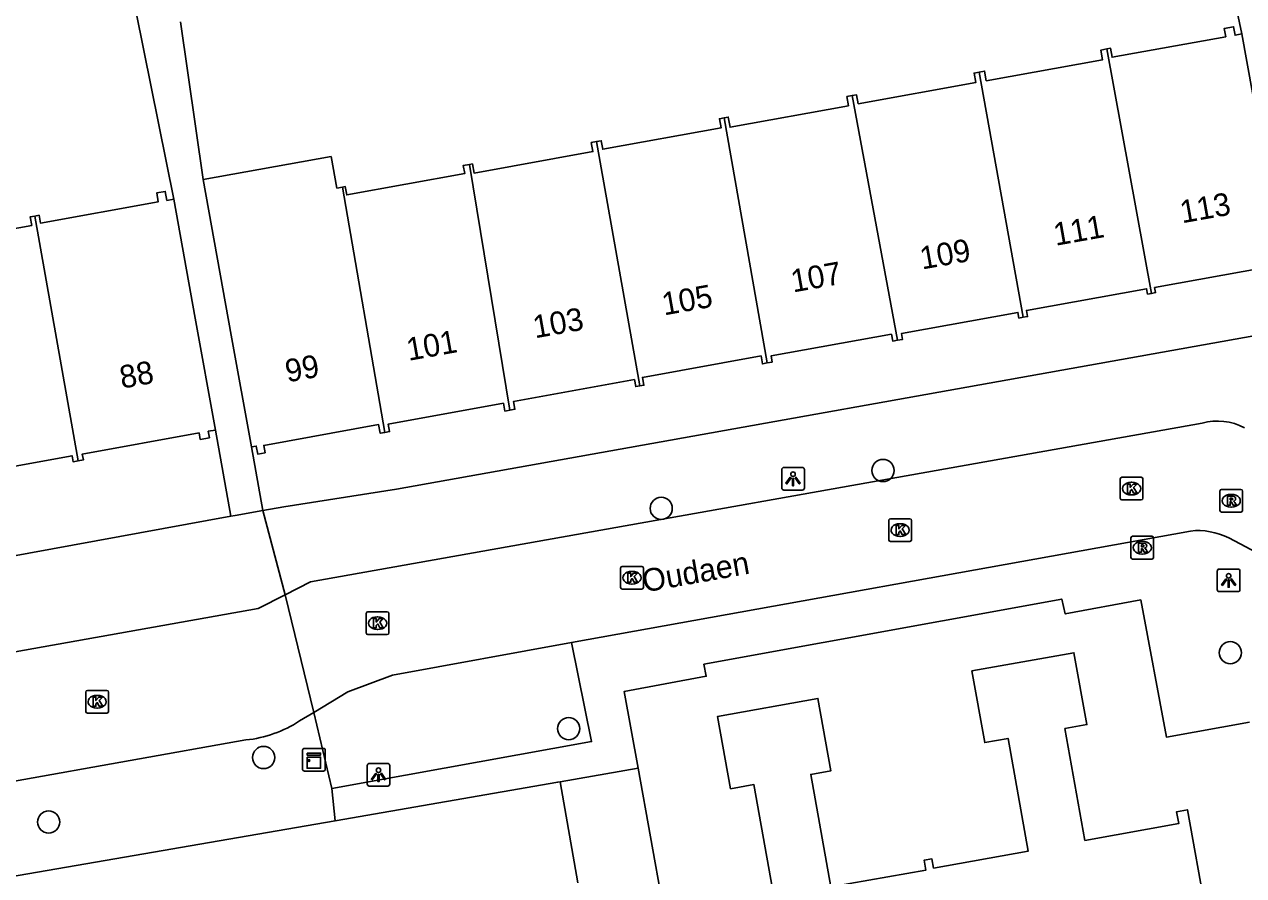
# Model space of a CAD drawing. Extents: x 157793 to 159380, y 380882 to 382313.
# Drawn here: x 158378.2 to 158431.9, y 381426.5 to 381464 of the extents above; entities that cross this region are included whole.
import ezdxf

# ---------------------------------------------------------------- set-up
doc = ezdxf.new("R2010")
doc.units = 0
for name, color, linetype in [('IMGEO_Boom', 7, 'Continuous'), ('IMGEO_Kast', 7, 'Continuous'), ('IMGEO_Kolk', 7, 'Continuous'), ('IMGEO_Lichtpunt', 7, 'Continuous'), ('IMGEO_Openbare_ruimte_label', 7, 'Continuous'), ('IMGEO_Pand', 7, 'Continuous'), ('IMGEO_Pand_nummerreeks', 7, 'Continuous'), ('IMGEO_Rijbaan_lokaal_open', 7, 'Continuous'), ('IMGEO_Rioolput', 7, 'Continuous'), ('IMGEO_Voetpad_open', 7, 'Continuous')]:
    doc.layers.add(name, color=color, linetype=linetype)

msp = doc.modelspace()

# ---------------------------------------------------------------- linework, layer by layer
at = {"layer": 'IMGEO_Boom'}
for centre in [(158416.009, 381444.352), (158406.245, 381442.684), (158431.298, 381436.33), (158402.174, 381432.988), (158388.741, 381431.716), (158379.274, 381428.878)]:
    msp.add_circle(centre, 0.489, dxfattribs=at)
at = {"layer": 'IMGEO_Kast'}
for p, q in [((158390.455, 381431.196), (158390.455, 381432.037)), ((158390.455, 381432.037), (158390.455, 381431.196)), ((158390.53, 381432.121), (158391.371, 381432.121)), ((158391.371, 381432.121), (158390.53, 381432.121)), ((158391.455, 381432.046), (158391.455, 381431.205)), ((158391.455, 381431.205), (158391.455, 381432.046)), ((158391.38, 381431.121), (158390.539, 381431.121)), ((158390.539, 381431.121), (158391.38, 381431.121))]:
    msp.add_line(p, q, dxfattribs=at)
for points in [[(158390.65, 381431.911), (158391.25, 381431.911), (158391.25, 381431.826), (158390.65, 381431.826), (158390.65, 381431.911)], [(158390.65, 381431.736), (158391.25, 381431.736), (158391.25, 381431.247), (158390.65, 381431.247), (158390.65, 381431.736)]]:
    msp.add_lwpolyline(points, dxfattribs=at)
msp.add_circle((158390.734, 381431.585), 0.0377, dxfattribs=at)
for centre, start, end in [((158390.533, 381432.043), 92.4484, 184.2845), ((158390.533, 381432.043), 92.4484, 184.2845), ((158391.377, 381432.043), 2.4484, 94.2845), ((158391.377, 381432.043), 2.4484, 94.2845), ((158390.533, 381431.199), 182.4484, 274.2845), ((158390.533, 381431.199), 182.4484, 274.2845), ((158391.377, 381431.199), 272.4484, 4.2845), ((158391.377, 381431.199), 272.4484, 4.2845)]:
    msp.add_arc(centre, 0.0779, start, end, dxfattribs=at)
at = {"layer": 'IMGEO_Kolk'}
for p, q in [((158426.452, 381443.131), (158426.452, 381443.983)), ((158426.527, 381444.057), (158427.379, 381444.057)), ((158426.94, 381443.837), (158426.965, 381443.837)), ((158427.453, 381443.983), (158427.453, 381443.131)), ((158426.963, 381443.277), (158426.938, 381443.277)), ((158427.379, 381443.057), (158426.527, 381443.057)), ((158416.263, 381441.304), (158416.263, 381442.156)), ((158416.338, 381442.23), (158417.19, 381442.23)), ((158416.751, 381442.01), (158416.776, 381442.01)), ((158417.264, 381442.156), (158417.264, 381441.304)), ((158416.774, 381441.45), (158416.749, 381441.45)), ((158417.19, 381441.23), (158416.338, 381441.23)), ((158404.457, 381439.206), (158404.457, 381440.058)), ((158404.532, 381440.132), (158405.384, 381440.132)), ((158404.945, 381439.912), (158404.97, 381439.912)), ((158405.458, 381440.058), (158405.458, 381439.206)), ((158404.968, 381439.352), (158404.943, 381439.352)), ((158405.384, 381439.132), (158404.532, 381439.132)), ((158393.257, 381437.205), (158393.257, 381438.057)), ((158393.332, 381438.131), (158394.184, 381438.131)), ((158393.745, 381437.911), (158393.77, 381437.911)), ((158394.258, 381438.057), (158394.258, 381437.205)), ((158393.768, 381437.351), (158393.743, 381437.351)), ((158394.184, 381437.131), (158393.332, 381437.131)), ((158380.909, 381433.748), (158380.909, 381434.6)), ((158380.984, 381434.674), (158381.836, 381434.674)), ((158381.91, 381434.6), (158381.91, 381433.748)), ((158381.397, 381434.454), (158381.422, 381434.454)), ((158381.836, 381433.674), (158380.984, 381433.674)), ((158381.42, 381433.894), (158381.395, 381433.894))]:
    msp.add_line(p, q, dxfattribs=at)
for points in [[(158426.452, 381443.131), (158426.452, 381443.983)], [(158426.527, 381444.057), (158427.379, 381444.057)], [(158426.773, 381443.757), (158426.896, 381443.757), (158426.896, 381443.606), (158427.026, 381443.757), (158427.19, 381443.757), (158427.044, 381443.606), (158427.197, 381443.357), (158427.045, 381443.357), (158426.96, 381443.521), (158426.896, 381443.454), (158426.896, 381443.357), (158426.773, 381443.357), (158426.773, 381443.757)], [(158427.453, 381443.983), (158427.453, 381443.131)], [(158427.379, 381443.057), (158426.527, 381443.057)], [(158416.263, 381441.304), (158416.263, 381442.156)], [(158416.338, 381442.23), (158417.19, 381442.23)], [(158417.264, 381442.156), (158417.264, 381441.304)], [(158416.584, 381441.93), (158416.707, 381441.93), (158416.707, 381441.779), (158416.837, 381441.93), (158417.001, 381441.93), (158416.855, 381441.779), (158417.008, 381441.53), (158416.856, 381441.53), (158416.771, 381441.694), (158416.707, 381441.627), (158416.707, 381441.53), (158416.584, 381441.53), (158416.584, 381441.93)], [(158417.19, 381441.23), (158416.338, 381441.23)], [(158404.457, 381439.206), (158404.457, 381440.058)], [(158404.532, 381440.132), (158405.384, 381440.132)], [(158405.458, 381440.058), (158405.458, 381439.206)], [(158404.778, 381439.832), (158404.901, 381439.832), (158404.901, 381439.681), (158405.031, 381439.832), (158405.195, 381439.832), (158405.049, 381439.681), (158405.202, 381439.432), (158405.05, 381439.432), (158404.965, 381439.596), (158404.901, 381439.529), (158404.901, 381439.432), (158404.778, 381439.432), (158404.778, 381439.832)], [(158405.384, 381439.132), (158404.532, 381439.132)], [(158393.257, 381437.205), (158393.257, 381438.057)], [(158393.332, 381438.131), (158394.184, 381438.131)], [(158393.578, 381437.831), (158393.701, 381437.831), (158393.701, 381437.68), (158393.831, 381437.831), (158393.995, 381437.831), (158393.849, 381437.68), (158394.002, 381437.431), (158393.85, 381437.431), (158393.765, 381437.595), (158393.701, 381437.528), (158393.701, 381437.431), (158393.578, 381437.431), (158393.578, 381437.831)], [(158394.258, 381438.057), (158394.258, 381437.205)], [(158394.184, 381437.131), (158393.332, 381437.131)], [(158380.909, 381433.748), (158380.909, 381434.6)], [(158380.984, 381434.674), (158381.836, 381434.674)], [(158381.91, 381434.6), (158381.91, 381433.748)], [(158381.23, 381434.374), (158381.353, 381434.374), (158381.353, 381434.223), (158381.483, 381434.374), (158381.647, 381434.374), (158381.501, 381434.223), (158381.654, 381433.974), (158381.502, 381433.974), (158381.417, 381434.138), (158381.353, 381434.071), (158381.353, 381433.974), (158381.23, 381433.974), (158381.23, 381434.374)], [(158381.836, 381433.674), (158380.984, 381433.674)]]:
    msp.add_lwpolyline(points, dxfattribs=at)
for centre, start, end in [((158426.529, 381443.981), 91.552, 178.448), ((158426.529, 381443.981), 91.552, 178.448), ((158427.377, 381443.981), 1.552, 88.448), ((158427.377, 381443.981), 1.552, 88.448), ((158426.529, 381443.133), 181.552, 268.448), ((158426.529, 381443.133), 181.552, 268.448), ((158427.377, 381443.133), 271.552, 358.448), ((158427.377, 381443.133), 271.552, 358.448), ((158416.34, 381442.154), 91.552, 178.448), ((158416.34, 381442.154), 91.552, 178.448), ((158417.188, 381442.154), 1.552, 88.448), ((158417.188, 381442.154), 1.552, 88.448), ((158416.34, 381441.306), 181.552, 268.448), ((158416.34, 381441.306), 181.552, 268.448), ((158417.188, 381441.306), 271.552, 358.448), ((158417.188, 381441.306), 271.552, 358.448), ((158404.534, 381440.056), 91.552, 178.448), ((158404.534, 381440.056), 91.552, 178.448), ((158405.382, 381440.056), 1.552, 88.448), ((158405.382, 381440.056), 1.552, 88.448), ((158404.534, 381439.208), 181.552, 268.448), ((158404.534, 381439.208), 181.552, 268.448), ((158405.382, 381439.208), 271.552, 358.448), ((158405.382, 381439.208), 271.552, 358.448), ((158393.334, 381438.055), 91.552, 178.448), ((158393.334, 381438.055), 91.552, 178.448), ((158394.182, 381438.055), 1.552, 88.448), ((158394.182, 381438.055), 1.552, 88.448), ((158393.334, 381437.207), 181.552, 268.448), ((158393.334, 381437.207), 181.552, 268.448), ((158394.182, 381437.207), 271.552, 358.448), ((158394.182, 381437.207), 271.552, 358.448), ((158380.986, 381434.598), 91.552, 178.448), ((158380.986, 381434.598), 91.552, 178.448), ((158381.834, 381434.598), 1.552, 88.448), ((158381.834, 381434.598), 1.552, 88.448), ((158380.986, 381433.75), 181.552, 268.448), ((158380.986, 381433.75), 181.552, 268.448), ((158381.834, 381433.75), 271.552, 358.448), ((158381.834, 381433.75), 271.552, 358.448)]:
    msp.add_arc(centre, 0.0765, start, end, dxfattribs=at)
for centre, major_axis, ratio, start_param, end_param in [((158426.939, 381443.557), (-0.387, 0.002), 0.722429, 4.712389, 7.853982), ((158426.964, 381443.557), (-0.39, 0.002), 0.717154, 1.570796, 4.712389), ((158416.75, 381441.73), (-0.387, 0.002), 0.722429, 4.712389, 7.853982), ((158416.775, 381441.73), (-0.39, 0.002), 0.717154, 1.570796, 4.712389), ((158404.944, 381439.632), (-0.387, 0.002), 0.722429, 4.712389, 7.853982), ((158404.969, 381439.632), (-0.39, 0.002), 0.717154, 1.570796, 4.712389), ((158393.744, 381437.631), (-0.387, 0.002), 0.722429, 4.712389, 7.853982), ((158393.769, 381437.631), (-0.39, 0.002), 0.717154, 1.570796, 4.712389), ((158381.396, 381434.174), (-0.387, 0.002), 0.722429, 4.712389, 7.853982), ((158381.421, 381434.174), (-0.39, 0.002), 0.717154, 1.570796, 4.712389)]:
    msp.add_ellipse(centre, major_axis=major_axis, ratio=ratio, start_param=start_param, end_param=end_param, dxfattribs=at)
at = {"layer": 'IMGEO_Lichtpunt'}
for p, q in [((158411.551, 381444.39), (158411.551, 381443.583)), ((158411.551, 381444.39), (158411.551, 381443.583)), ((158412.453, 381444.485), (158411.645, 381444.485)), ((158412.453, 381444.485), (158411.645, 381444.485)), ((158412.547, 381443.583), (158412.547, 381444.39)), ((158412.547, 381443.583), (158412.547, 381444.39)), ((158411.645, 381443.489), (158412.453, 381443.489)), ((158411.645, 381443.489), (158412.453, 381443.489)), ((158430.729, 381439.92), (158430.729, 381439.113)), ((158430.729, 381439.92), (158430.729, 381439.113)), ((158431.631, 381440.015), (158430.823, 381440.015)), ((158431.631, 381440.015), (158430.823, 381440.015)), ((158431.725, 381439.113), (158431.725, 381439.92)), ((158431.725, 381439.113), (158431.725, 381439.92)), ((158430.823, 381439.019), (158431.631, 381439.019)), ((158430.823, 381439.019), (158431.631, 381439.019)), ((158393.299, 381431.36), (158393.299, 381430.553)), ((158393.299, 381431.36), (158393.299, 381430.553)), ((158394.201, 381431.455), (158393.393, 381431.455)), ((158394.201, 381431.455), (158393.393, 381431.455)), ((158394.295, 381430.553), (158394.295, 381431.36)), ((158394.295, 381430.553), (158394.295, 381431.36)), ((158393.393, 381430.459), (158394.201, 381430.459)), ((158393.393, 381430.459), (158394.201, 381430.459))]:
    msp.add_line(p, q, dxfattribs=at)
for points in [[(158411.925, 381444.054), (158411.964, 381444.026), (158411.776, 381443.764), (158411.738, 381443.791), (158411.925, 381444.054)], [(158412.027, 381444.006), (158412.074, 381444.006), (158412.074, 381443.684), (158412.027, 381443.684), (158412.027, 381444.006)], [(158412.137, 381444.026), (158412.175, 381444.053), (158412.362, 381443.791), (158412.323, 381443.763), (158412.137, 381444.026)], [(158431.103, 381439.584), (158431.142, 381439.556), (158430.954, 381439.294), (158430.916, 381439.321), (158431.103, 381439.584)], [(158431.205, 381439.536), (158431.252, 381439.536), (158431.252, 381439.214), (158431.205, 381439.214), (158431.205, 381439.536)], [(158431.315, 381439.556), (158431.353, 381439.583), (158431.54, 381439.321), (158431.501, 381439.293), (158431.315, 381439.556)], [(158393.673, 381431.024), (158393.712, 381430.996), (158393.524, 381430.734), (158393.486, 381430.761), (158393.673, 381431.024)], [(158393.775, 381430.976), (158393.822, 381430.976), (158393.822, 381430.654), (158393.775, 381430.654), (158393.775, 381430.976)], [(158393.885, 381430.996), (158393.923, 381431.023), (158394.11, 381430.761), (158394.071, 381430.733), (158393.885, 381430.996)]]:
    msp.add_lwpolyline(points, dxfattribs=at)
for centre in [(158412.05, 381444.188), (158431.228, 381439.718), (158393.798, 381431.158)]:
    msp.add_circle(centre, 0.0994, dxfattribs=at)
for centre, start, end in [((158411.645, 381444.39), 90, 180), ((158411.645, 381444.39), 90, 180), ((158412.453, 381444.39), 0, 90), ((158412.453, 381444.39), 0, 90), ((158411.645, 381443.583), 180, 270), ((158411.645, 381443.583), 180, 270), ((158412.453, 381443.583), 270, 0), ((158412.453, 381443.583), 270, 360), ((158430.823, 381439.92), 90, 180), ((158430.823, 381439.92), 90, 180), ((158431.631, 381439.92), 0, 90), ((158431.631, 381439.92), 0, 90), ((158430.823, 381439.113), 180, 270), ((158430.823, 381439.113), 180, 270), ((158431.631, 381439.113), 270, 0), ((158431.631, 381439.113), 270, 360), ((158393.393, 381431.36), 90, 180), ((158393.393, 381431.36), 90, 180), ((158394.201, 381431.36), 0, 90), ((158394.201, 381431.36), 0, 90), ((158393.393, 381430.553), 180, 270), ((158393.393, 381430.553), 180, 270), ((158394.201, 381430.553), 270, 0), ((158394.201, 381430.553), 270, 360)]:
    msp.add_arc(centre, 0.0946, start, end, dxfattribs=at)
at = {"layer": 'IMGEO_Pand'}
for points in [[(158425.859, 381462.909), (158426.027, 381462.939), (158426.098, 381462.546), (158431.102, 381463.448), (158431.037, 381463.811), (158431.442, 381463.884), (158431.508, 381463.515), (158431.813, 381463.57)], [(158431.813, 381463.57), (158432.748, 381458.386), (158433.635, 381453.465)], [(158420.248, 381461.892), (158420.481, 381461.934), (158420.558, 381461.511), (158425.678, 381462.435), (158425.601, 381462.862), (158425.859, 381462.909)], [(158425.859, 381462.909), (158427.832, 381452.15)], [(158414.649, 381460.855), (158414.845, 381460.89), (158414.916, 381460.498), (158420.093, 381461.432), (158420.017, 381461.85), (158420.248, 381461.892)], [(158420.248, 381461.892), (158422.18, 381451.096)], [(158409.018, 381459.878), (158409.196, 381459.91), (158409.276, 381459.466), (158414.49, 381460.406), (158414.417, 381460.813), (158414.649, 381460.855)], [(158416.652, 381450.086), (158414.649, 381460.855)], [(158403.401, 381458.834), (158403.606, 381458.871), (158403.674, 381458.493), (158408.881, 381459.432), (158408.808, 381459.84), (158409.018, 381459.878)], [(158409.018, 381459.878), (158410.914, 381449.086)], [(158397.806, 381457.83), (158397.929, 381457.852), (158398.002, 381457.448), (158403.238, 381458.393), (158403.166, 381458.791), (158403.401, 381458.834)], [(158405.299, 381448.075), (158403.401, 381458.834)], [(158386.078, 381457.157), (158391.713, 381458.173), (158391.964, 381456.782), (158392.212, 381456.827)], [(158392.212, 381456.827), (158392.337, 381456.849), (158392.403, 381456.485), (158397.592, 381457.421), (158397.527, 381457.78), (158397.806, 381457.83)], [(158397.806, 381457.83), (158399.582, 381447.01)], [(158388.2, 381445.387), (158387.313, 381450.308), (158386.078, 381457.157)], [(158378.663, 381455.555), (158378.85, 381455.589), (158378.912, 381455.245), (158384.102, 381456.181), (158384.032, 381456.57), (158384.408, 381456.638), (158384.479, 381456.244), (158384.783, 381456.299)], [(158394.077, 381446.026), (158392.212, 381456.827)], [(158384.783, 381456.299), (158385.729, 381451.056), (158386.616, 381446.135)], [(158373.079, 381454.549), (158373.374, 381454.602), (158373.442, 381454.225), (158378.533, 381455.143), (158378.465, 381455.52), (158378.663, 381455.555)], [(158378.663, 381455.555), (158380.579, 381444.777)], [(158433.635, 381453.465), (158433.354, 381453.415), (158433.401, 381453.155), (158432.958, 381453.075), (158432.918, 381453.298), (158427.97, 381452.406), (158428.011, 381452.182), (158427.832, 381452.15)], [(158427.832, 381452.15), (158427.656, 381452.118), (158427.613, 381452.353), (158422.324, 381451.399), (158422.372, 381451.131), (158422.18, 381451.096)], [(158422.18, 381451.096), (158421.992, 381451.062), (158421.948, 381451.308), (158416.825, 381450.384), (158416.871, 381450.125), (158416.652, 381450.086)], [(158416.652, 381450.086), (158416.436, 381450.047), (158416.381, 381450.352), (158411.079, 381449.396), (158411.128, 381449.125), (158410.914, 381449.086)], [(158410.914, 381449.086), (158410.7, 381449.047), (158410.638, 381449.393), (158405.419, 381448.452), (158405.481, 381448.108), (158405.299, 381448.075)], [(158405.299, 381448.075), (158405.12, 381448.043), (158405.064, 381448.355), (158399.743, 381447.396), (158399.805, 381447.05), (158399.582, 381447.01)], [(158399.582, 381447.01), (158399.36, 381446.97), (158399.298, 381447.314), (158394.223, 381446.399), (158394.283, 381446.063), (158394.077, 381446.026)], [(158394.077, 381446.026), (158393.872, 381445.989), (158393.803, 381446.37), (158388.747, 381445.459), (158388.805, 381445.137), (158388.48, 381445.078), (158388.417, 381445.426), (158388.2, 381445.387)], [(158386.616, 381446.135), (158386.303, 381446.079), (158386.354, 381445.795), (158385.946, 381445.721), (158385.895, 381446.005), (158380.757, 381445.078), (158380.804, 381444.817), (158380.579, 381444.777)], [(158380.579, 381444.777), (158380.353, 381444.736), (158380.305, 381445.003), (158375.271, 381444.095), (158375.324, 381443.803), (158375.115, 381443.765)], [(158430.22, 381424.917), (158429.415, 381429.417), (158428.937, 381429.331), (158429.031, 381428.805), (158424.901, 381428.067), (158424.02, 381432.992), (158424.985, 381433.164), (158424.418, 381436.331), (158419.926, 381435.528), (158420.49, 381432.376), (158421.517, 381432.559), (158422.404, 381427.597), (158418.237, 381426.852), (158418.165, 381427.255), (158417.821, 381427.193), (158417.897, 381426.765), (158413.715, 381426.018), (158412.829, 381430.973), (158413.714, 381431.131), (158413.145, 381434.317), (158408.727, 381433.527), (158409.297, 381430.341), (158410.323, 381430.524), (158411.216, 381425.529)]]:
    msp.add_lwpolyline(points, dxfattribs=at)
at = {"layer": 'IMGEO_Rijbaan_lokaal_open'}
for points in [[(158389.687, 381438.882), (158390.797, 381439.449), (158430.056, 381446.433)], [(158429.544, 381441.688), (158402.292, 381436.775)], [(158438.575, 381437.502), (158431.233, 381441.393)], [(158389.687, 381438.882), (158388.503, 381438.277), (158347.078, 381430.896), (158347.04, 381431.137)], [(158390.946, 381433.696), (158389.687, 381438.882)], [(158390.946, 381433.696), (158392.45, 381434.61), (158394.416, 381435.342), (158402.292, 381436.775)], [(158390.318, 381433.326), (158390.946, 381433.696)], [(158372.662, 381429.759), (158387.962, 381432.489)]]:
    msp.add_lwpolyline(points, dxfattribs=at)
for centre, radius, start, end in [((158430.744, 381444.006), 2.522, 61.8879, 105.8207), ((158429.873, 381438.59), 3.116, 64.122, 96.0634), ((158387.396, 381437.818), 5.359, 276.068, 303.0485)]:
    msp.add_arc(centre, radius, start, end, dxfattribs=at)
at = {"layer": 'IMGEO_Rioolput'}
for p, q in [((158430.839, 381442.593), (158430.839, 381443.445)), ((158430.914, 381443.519), (158431.766, 381443.519)), ((158431.327, 381443.299), (158431.352, 381443.299)), ((158431.84, 381443.445), (158431.84, 381442.593)), ((158431.35, 381442.739), (158431.325, 381442.739)), ((158431.766, 381442.519), (158430.914, 381442.519)), ((158426.999, 381441.455), (158427.851, 381441.455)), ((158426.924, 381440.529), (158426.924, 381441.381)), ((158427.412, 381441.235), (158427.437, 381441.235)), ((158427.925, 381441.381), (158427.925, 381440.529)), ((158427.851, 381440.455), (158426.999, 381440.455)), ((158427.435, 381440.675), (158427.41, 381440.675))]:
    msp.add_line(p, q, dxfattribs=at)
for points in [[(158430.839, 381442.593), (158430.839, 381443.445)], [(158430.914, 381443.519), (158431.766, 381443.519)], [(158431.428, 381443.217), (158431.176, 381443.219), (158431.176, 381442.819)], [(158431.354, 381443.138), (158431.3, 381443.138), (158431.3, 381443.057)], [(158431.84, 381443.445), (158431.84, 381442.593)], [(158431.176, 381442.819), (158431.3, 381442.819), (158431.3, 381442.981), (158431.311, 381442.981)], [(158431.3, 381443.057), (158431.352, 381443.057)], [(158431.358, 381442.952), (158431.429, 381442.819), (158431.569, 381442.819), (158431.504, 381442.945)], [(158431.766, 381442.519), (158430.914, 381442.519)], [(158426.999, 381441.455), (158427.851, 381441.455)], [(158426.924, 381440.529), (158426.924, 381441.381)], [(158427.513, 381441.153), (158427.261, 381441.155), (158427.261, 381440.755)], [(158427.261, 381440.755), (158427.385, 381440.755), (158427.385, 381440.917), (158427.396, 381440.917)], [(158427.439, 381441.074), (158427.385, 381441.074), (158427.385, 381440.993)], [(158427.385, 381440.993), (158427.437, 381440.993)], [(158427.925, 381441.381), (158427.925, 381440.529)], [(158427.851, 381440.455), (158426.999, 381440.455)], [(158427.443, 381440.888), (158427.514, 381440.755), (158427.654, 381440.755), (158427.589, 381440.881)]]:
    msp.add_lwpolyline(points, dxfattribs=at)
for centre, radius, start, end in [((158430.916, 381443.443), 0.0765, 91.552, 178.448), ((158430.916, 381443.443), 0.0765, 91.552, 178.448), ((158431.336, 381443.246), 0.19, 274.7715, 282.9687), ((158431.36, 381443.042), 0.0964, 77.0061, 93.1865), ((158431.374, 381443.099), 0.0378, 276.6634, 79.6772), ((158431.427, 381443.107), 0.109, 350.3612, 89.416), ((158431.425, 381443.107), 0.112, 277.5842, 350.9817), ((158431.764, 381443.443), 0.0765, 1.552, 88.448), ((158431.764, 381443.443), 0.0765, 1.552, 88.448), ((158430.916, 381442.595), 0.0765, 181.552, 268.448), ((158430.916, 381442.595), 0.0765, 181.552, 268.448), ((158431.31, 381442.928), 0.0533, 26.0293, 88.6989), ((158431.409, 381442.892), 0.108, 29.5134, 73.7905), ((158431.764, 381442.595), 0.0765, 271.552, 358.448), ((158431.764, 381442.595), 0.0765, 271.552, 358.448), ((158427.001, 381441.379), 0.0765, 91.552, 178.448), ((158427.001, 381441.379), 0.0765, 91.552, 178.448), ((158427.849, 381441.379), 0.0765, 1.552, 88.448), ((158427.849, 381441.379), 0.0765, 1.552, 88.448), ((158427.395, 381440.864), 0.0533, 26.0293, 88.6989), ((158427.421, 381441.182), 0.19, 274.7715, 282.9687), ((158427.445, 381440.978), 0.0964, 77.0061, 93.1865), ((158427.459, 381441.035), 0.0378, 276.6634, 79.6772), ((158427.512, 381441.043), 0.109, 350.3612, 89.416), ((158427.51, 381441.043), 0.112, 277.5842, 350.9817), ((158427.494, 381440.828), 0.108, 29.5134, 73.7905), ((158427.001, 381440.531), 0.0765, 181.552, 268.448), ((158427.001, 381440.531), 0.0765, 181.552, 268.448), ((158427.849, 381440.531), 0.0765, 271.552, 358.448), ((158427.849, 381440.531), 0.0765, 271.552, 358.448)]:
    msp.add_arc(centre, radius, start, end, dxfattribs=at)
for centre, major_axis, ratio, start_param, end_param in [((158431.326, 381443.019), (-0.387, 0.002), 0.722429, 4.712389, 7.853982), ((158431.351, 381443.019), (-0.39, 0.002), 0.717154, 1.570796, 4.712389), ((158427.411, 381440.955), (-0.387, 0.002), 0.722429, 4.712389, 7.853982), ((158427.436, 381440.955), (-0.39, 0.002), 0.717154, 1.570796, 4.712389)]:
    msp.add_ellipse(centre, major_axis=major_axis, ratio=ratio, start_param=start_param, end_param=end_param, dxfattribs=at)
at = {"layer": 'IMGEO_Voetpad_open'}
for points in [[(158429.986, 381472.195), (158431.813, 381463.57)], [(158381.791, 381471.153), (158384.783, 381456.299)], [(158386.078, 381457.157), (158385.085, 381464.099)], [(158434.145, 381450.6), (158394.586, 381443.534), (158389.628, 381442.752), (158388.705, 381442.588)], [(158386.616, 381446.135), (158387.301, 381442.337)], [(158388.705, 381442.588), (158388.2, 381445.387)], [(158387.301, 381442.337), (158387.491, 381442.372), (158388.705, 381442.588)], [(158388.705, 381442.588), (158389.687, 381438.882)], [(158387.301, 381442.337), (158353.628, 381436.175), (158352.398, 381435.95), (158347.332, 381435.023), (158347.326, 381435.057)], [(158405.232, 381431.245), (158404.617, 381434.627), (158408.23, 381435.291), (158408.121, 381435.824), (158423.88, 381438.688), (158424.032, 381438.042), (158427.357, 381438.657), (158428.488, 381432.615), (158432.139, 381433.276)], [(158402.292, 381436.775), (158403.177, 381432.417), (158391.741, 381430.36)], [(158391.741, 381430.36), (158390.946, 381433.696)], [(158401.802, 381430.651), (158405.232, 381431.245)], [(158406.31, 381425.206), (158405.232, 381431.245)], [(158391.741, 381430.36), (158391.883, 381428.934)], [(158401.802, 381430.651), (158401.691, 381430.632), (158391.883, 381428.934)], [(158402.574, 381426.193), (158401.802, 381430.651)], [(158391.883, 381428.934), (158377.508, 381426.445), (158376.475, 381425.963)]]:
    msp.add_lwpolyline(points, dxfattribs=at)

# ---------------------------------------------------------------- texts
at = {"layer": 'IMGEO_Openbare_ruimte_label'}
msp.add_text('Oudaen', height=1, rotation=10.1408, dxfattribs=at).set_placement((158405.505, 381438.982))
at = {"layer": 'IMGEO_Pand_nummerreeks'}
for s, rotation, p in [('113', 10.0814, (158429.178, 381455.232)), ('111', 10.0814, (158423.609, 381454.243)), ('109', 10.0814, (158417.728, 381453.197)), ('107', 10.0814, (158412.049, 381452.187)), ('105', 10.0814, (158406.369, 381451.177)), ('103', 10.0814, (158400.69, 381450.168)), ('101', 10.0814, (158395.123, 381449.178)), ('88', 10.25, (158382.499, 381447.952)), ('99', 10.0814, (158389.785, 381448.228))]:
    msp.add_text(s, height=1, rotation=rotation, dxfattribs=at).set_placement(p)

doc.saveas('drawing.dxf')
